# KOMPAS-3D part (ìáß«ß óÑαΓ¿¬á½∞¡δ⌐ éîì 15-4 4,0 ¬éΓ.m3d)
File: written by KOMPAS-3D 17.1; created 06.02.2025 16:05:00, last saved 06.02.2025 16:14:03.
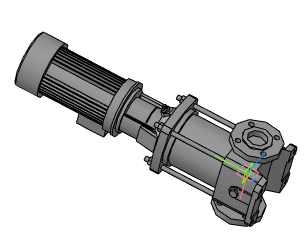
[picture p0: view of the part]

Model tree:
1. Операция без истории:1  (labels: Насос вертикальный ВМН 15-4 4,0 кВт)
